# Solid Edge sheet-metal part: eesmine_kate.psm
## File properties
Author: Blackblade
Template: Normal.psm
Last saved by: Blackblade
Revision: 3
Application: Solid Edge
Accuracy: 0.990
Material Thickness: 1.00 mm
Bend Radius: 1.00 mm
Relief Width: 1.00 mm
Relief Length: 0.00 mm
Neutral Factor: 0.330
Minimum Arc Length: 0.10 mm
Deviational Tolerance: 0.10 mm
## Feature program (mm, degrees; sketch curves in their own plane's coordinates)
base tab "unnamed BaseTab 1"
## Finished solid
Body 1: solid body, 5 faces, 9 edges, 6 vertices.
  Faces by surface: plane 3, cylinder 2
  Edges by curve: line 5, circle 4
Bounding box of the edges (mm): 263.111 x 141.989 x 1.000, from (101.6729, -71.4029, 0) to (364.7842, 70.5865, 1).
Cylindrical faces by radius (mm): R649 x2
Planar faces by outward normal: +z 1, -x 1, -z 1
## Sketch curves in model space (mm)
line (101.6729, -71.4029, 0) -> (101.6729, 70.5865, 0)
arc centre (67.9255, 576.7191, 0) radius 649 from (101.6729, -71.4029, 0) through (236.9969, -49.8715, 0) to (364.7842, -0.4082, 0)
arc centre (67.9255, -577.5355, 0) radius 649 from (364.7842, -0.4082, 0) through (236.9969, 49.0552, 0) to (101.6729, 70.5865, 0)
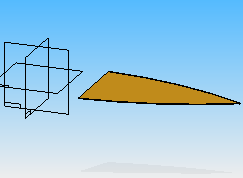
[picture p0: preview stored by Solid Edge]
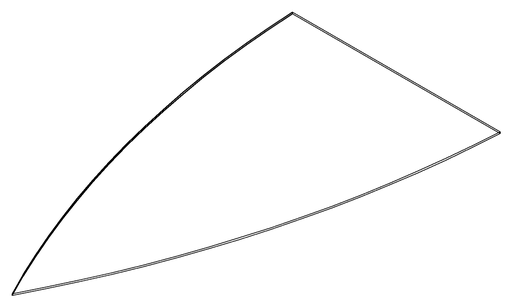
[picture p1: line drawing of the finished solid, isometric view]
